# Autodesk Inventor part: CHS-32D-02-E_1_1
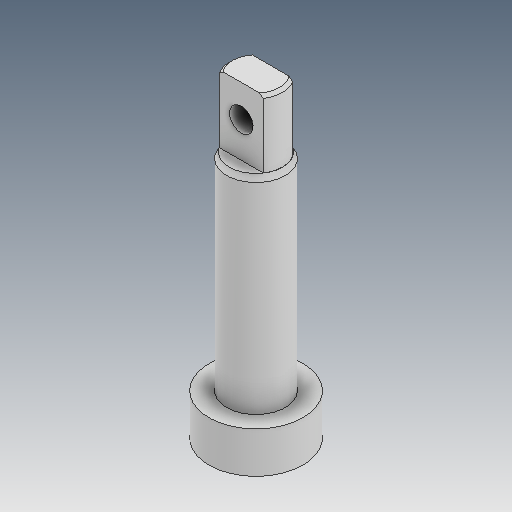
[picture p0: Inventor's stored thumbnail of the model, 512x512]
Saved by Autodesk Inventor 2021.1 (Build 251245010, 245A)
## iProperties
Created: 2021-05
Part Number: CHS-32D-02-E_1_1
Material: Ogólny
Document SubType Name: Modeling
Designer: user
Density: 1 g/cm^3
Appearance: Domyślna
Author: user
Revision Number: ÈÎºÎ
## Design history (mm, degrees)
feature "ÊäÈë1"
feature "ÊäÈë2"
node "Bryła1"
node "Bryła2"
